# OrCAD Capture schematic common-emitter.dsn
size A; title: Common Emitter Amplifier
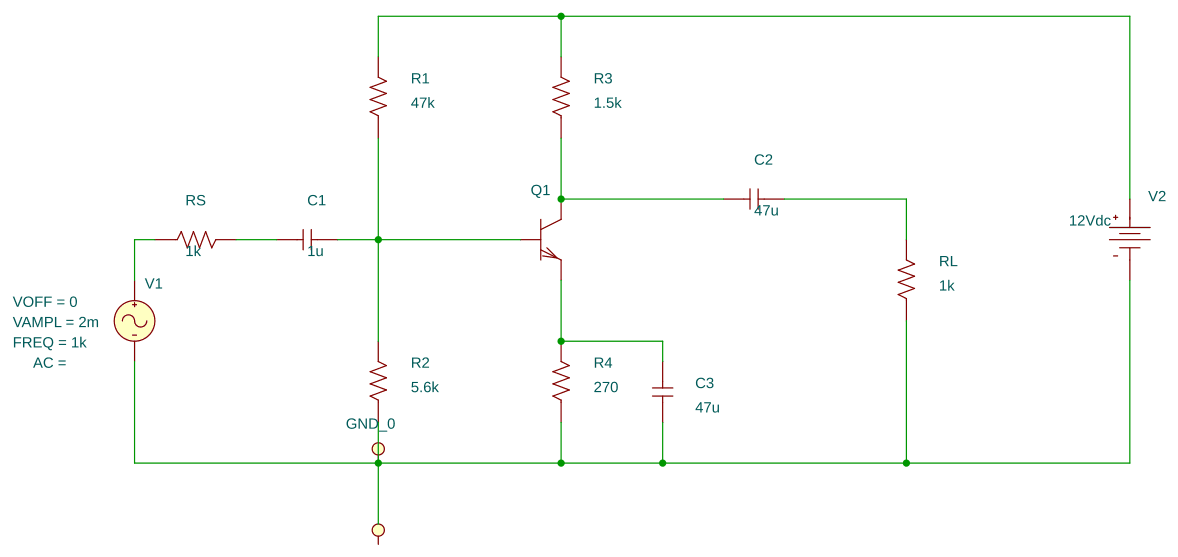
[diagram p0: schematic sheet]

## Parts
C1  1u  [cap196]
C2  47u  [cap196]
C3  47u  [cap196]
Q1  QbreakN
R1  47k  [AXRC05]
R2  5.6k  [AXRC05]
R3  1.5k  [AXRC05]
R4  270  [AXRC05]
RL  1k  [AXRC05]
RS  1k  [AXRC05]
V1  VSIN
V2  VDC

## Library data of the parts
C1-C3 = C
Q1 = QbreakN
R1-R4 RL RS = R
V1 = VSIN: FREQ: 1k; VAMPL: 2m; VOFF: 0
V2 = VDC: DC: 12Vdc

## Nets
0: C3.1 R2.1 R4.1 RL.1 V1.2(-) V2.1(-)
N14537: C1.2 Q1.0(b) R1.1 R2.2
N14607: C2.1 Q1.1(c) R3.1
N14611: C3.2 Q1.2(e) R4.2
N14661: C2.2 RL.2
N14758: R1.2 R3.2 V2.0(+)
N16141: C1.1 RS.2
N16145: RS.1 V1.1(+)
